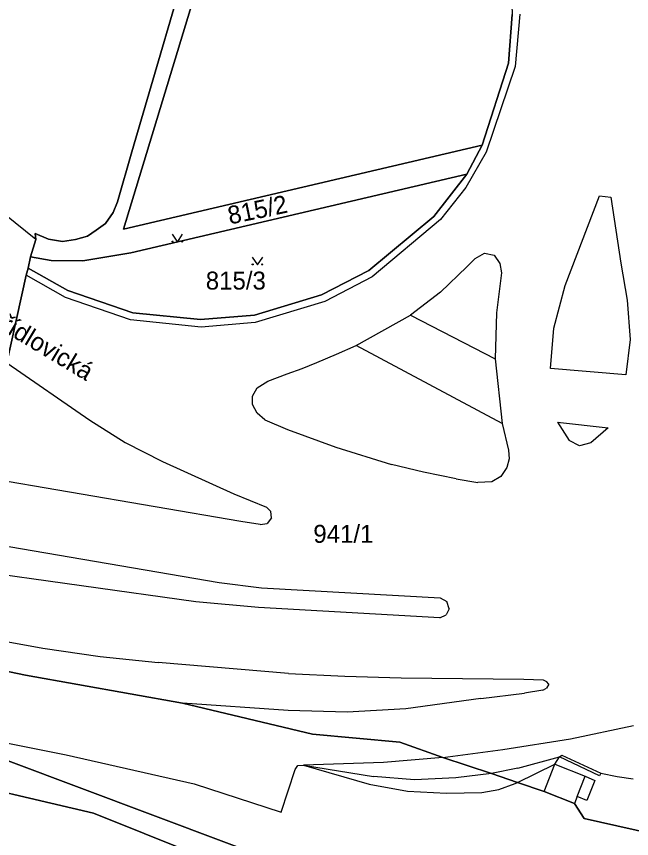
# Model space of a CAD drawing. Extents: x -598934 to -598196, y -1162208 to -1161502.
# Drawn here: x -598332.2 to -598274, y -1162056.4 to -1161978.6 of the extents above; entities that cross this region are included whole.
import ezdxf

# ---------------------------------------------------------------- set-up
doc = ezdxf.new("R2010")
doc.units = 0
for name, color, linetype in [('KN_CAR_KR', 7, 'Continuous'), ('KN_KULTURY', 7, 'Continuous'), ('KN_PARC_CIS_POM', 7, 'Continuous'), ('KN_PARC_CIS_POZ', 7, 'Continuous'), ('KN_PARC_PLOCHA', 7, 'Continuous'), ('KN_ULICE', 7, 'Continuous'), ('parcely_l', 7, 'Continuous')]:
    doc.layers.add(name, color=color, linetype=linetype)

msp = doc.modelspace()

# ---------------------------------------------------------------- linework, layer by layer
at = {"layer": 'KN_CAR_KR'}
for points in [[(-598330.34, -1161999.7), (-598362.46, -1161973.78)], [(-598284.56, -1161978.37), (-598284.98, -1161983.3)], [(-598284.98, -1161983.3), (-598287.75, -1161991.43)], [(-598287.75, -1161991.43), (-598289.66, -1161994.78)], [(-598289.66, -1161994.78), (-598292.05, -1161997.81)], [(-598280.26, -1162004.04), (-598277, -1161995.55)], [(-598277, -1161995.55), (-598275.94, -1161995.69)], [(-598275.94, -1161995.69), (-598275, -1162001.93)], [(-598292.05, -1161997.81), (-598298.51, -1162003.24)], [(-598288.78, -1162001.5), (-598287.89, -1162000.99)], [(-598287.89, -1162000.99), (-598286.98, -1162001.16)], [(-598286.98, -1162001.16), (-598286.44, -1162001.96)], [(-598289.55, -1162002.29), (-598288.78, -1162001.5)], [(-598286.44, -1162001.96), (-598286.27, -1162002.85)], [(-598275, -1162001.93), (-598274.38, -1162005.44)], [(-598289.55, -1162002.29), (-598292.05, -1162004.69)], [(-598286.27, -1162002.85), (-598286.75, -1162006.62)], [(-598327.56, -1162005.17), (-598331.27, -1162003.07)], [(-598298.51, -1162003.24), (-598303, -1162005.55)], [(-598281.32, -1162008.09), (-598280.26, -1162004.04)], [(-598321.4, -1162007.29), (-598327.56, -1162005.17)], [(-598292.05, -1162004.69), (-598294.9, -1162006.84)], [(-598303, -1162005.55), (-598309.61, -1162007.55)], [(-598274.38, -1162005.44), (-598274.12, -1162009.16)], [(-598286.75, -1162006.62), (-598286.89, -1162011)], [(-598314.7, -1162007.98), (-598321.4, -1162007.29)], [(-598309.61, -1162007.55), (-598314.7, -1162007.98)], [(-598300.04, -1162009.73), (-598294.9, -1162006.84)], [(-598294.9, -1162006.84), (-598286.89, -1162011)], [(-598281.66, -1162011.9), (-598281.32, -1162008.09)], [(-598301.9, -1162010.54), (-598300.04, -1162009.73)], [(-598286.23, -1162017.12), (-598300.04, -1162009.73)], [(-598274.12, -1162009.16), (-598274.51, -1162012.5)], [(-598303.76, -1162011.35), (-598301.9, -1162010.54)], [(-598333.11, -1162011.38), (-598325.26, -1162016.8)], [(-598305.16, -1162011.9), (-598303.76, -1162011.35)], [(-598286.89, -1162011), (-598286.23, -1162017.12)], [(-598306.57, -1162012.42), (-598305.16, -1162011.9)], [(-598274.51, -1162012.5), (-598281.66, -1162011.9)], [(-598308.39, -1162013.09), (-598306.57, -1162012.42)], [(-598309.86, -1162014.51), (-598309.42, -1162013.75)], [(-598309.42, -1162013.75), (-598308.39, -1162013.09)], [(-598309.86, -1162015.31), (-598309.86, -1162014.51)], [(-598309.42, -1162016.14), (-598309.86, -1162015.31)], [(-598308.69, -1162016.78), (-598309.42, -1162016.14)], [(-598325.26, -1162016.8), (-598321.9, -1162018.92)], [(-598308.69, -1162016.78), (-598306.54, -1162017.69)], [(-598306.54, -1162017.69), (-598301.97, -1162019.36)], [(-598286.23, -1162017.12), (-598285.62, -1162019.65)], [(-598280.97, -1162017), (-598276.2, -1162017.51)], [(-598280.97, -1162017), (-598279.88, -1162018.73)], [(-598276.2, -1162017.51), (-598277.82, -1162018.95)], [(-598321.9, -1162018.92), (-598318.37, -1162020.72)], [(-598278.91, -1162019.23), (-598279.88, -1162018.73)], [(-598277.82, -1162018.95), (-598278.91, -1162019.23)], [(-598301.97, -1162019.36), (-598296.7, -1162020.99)], [(-598285.62, -1162019.65), (-598285.56, -1162020.47)], [(-598318.37, -1162020.72), (-598311.61, -1162023.76)], [(-598285.56, -1162020.47), (-598285.79, -1162021.29)], [(-598293.65, -1162021.71), (-598296.7, -1162020.99)], [(-598285.79, -1162021.29), (-598286.36, -1162022.12)], [(-598310.94, -1162026.4), (-598335.31, -1162022.24)], [(-598290.58, -1162022.35), (-598293.65, -1162021.71)], [(-598290.58, -1162022.35), (-598288.53, -1162022.7)], [(-598286.36, -1162022.12), (-598287.19, -1162022.63)], [(-598287.19, -1162022.63), (-598288.53, -1162022.7)], [(-598311.61, -1162023.76), (-598308.51, -1162025.03)], [(-598308.51, -1162025.03), (-598308.1, -1162025.46)], [(-598308.05, -1162026.06), (-598308.1, -1162025.46)], [(-598308.05, -1162026.06), (-598308.46, -1162026.59)], [(-598309.12, -1162026.69), (-598310.94, -1162026.4)], [(-598309.12, -1162026.69), (-598308.46, -1162026.59)], [(-598336.43, -1162028.17), (-598312.99, -1162032.18)], [(-598315.2, -1162034.01), (-598336.9, -1162030.98)], [(-598312.99, -1162032.18), (-598309.01, -1162032.67)], [(-598309.01, -1162032.67), (-598292.09, -1162033.61)], [(-598309.28, -1162034.55), (-598315.2, -1162034.01)], [(-598292.09, -1162033.61), (-598291.45, -1162033.96)], [(-598291.25, -1162034.66), (-598291.45, -1162033.96)], [(-598292.11, -1162035.51), (-598309.28, -1162034.55)], [(-598291.25, -1162034.66), (-598291.53, -1162035.24)], [(-598292.11, -1162035.51), (-598291.53, -1162035.24)], [(-598338.01, -1162036.88), (-598329.7, -1162038.39)], [(-598329.7, -1162038.39), (-598324.26, -1162039.17)], [(-598324.26, -1162039.17), (-598318.79, -1162039.74)], [(-598306.43, -1162040.79), (-598318.79, -1162039.74)], [(-598306.43, -1162040.79), (-598301.11, -1162041.05)], [(-598301.11, -1162041.05), (-598295.78, -1162041.19)], [(-598295.78, -1162041.19), (-598284.17, -1162041.32)], [(-598284.17, -1162041.32), (-598282.33, -1162041.39)], [(-598282.33, -1162041.39), (-598282.01, -1162041.53)], [(-598281.79, -1162041.81), (-598282.01, -1162041.53)], [(-598281.79, -1162041.81), (-598282.01, -1162042.16)], [(-598282.38, -1162042.35), (-598284.1, -1162042.64)], [(-598282.38, -1162042.35), (-598282.01, -1162042.16)], [(-598288.24, -1162043.14), (-598295.33, -1162044.12)], [(-598288.24, -1162043.14), (-598284.1, -1162042.64)], [(-598306.47, -1162044.28), (-598316.47, -1162043.58)], [(-598295.33, -1162044.12), (-598300.9, -1162044.46)], [(-598300.9, -1162044.46), (-598306.47, -1162044.28)], [(-598279.75, -1162046.98), (-598273.78, -1162045.72)], [(-598339.66, -1162046.05), (-598327.47, -1162048.48)], [(-598286.15, -1162047.99), (-598279.75, -1162046.98)], [(-598291.83, -1162048.73), (-598286.15, -1162047.99)], [(-598327.47, -1162048.48), (-598315.37, -1162051.23)], [(-598291.83, -1162048.73), (-598297.45, -1162049.21)], [(-598284.75, -1162049.75), (-598280.79, -1162048.66)], [(-598281.23, -1162049.38), (-598280.79, -1162048.66)], [(-598280.79, -1162048.66), (-598280.56, -1162048.52)], [(-598277.01, -1162050.47), (-598280.79, -1162048.66)], [(-598280.56, -1162048.52), (-598276.87, -1162050.21)], [(-598305.8, -1162049.86), (-598305.56, -1162049.51)], [(-598305.56, -1162049.51), (-598305.01, -1162049.45)], [(-598297.45, -1162049.21), (-598305.01, -1162049.45)], [(-598305.01, -1162049.45), (-598298.39, -1162050.54)], [(-598305.01, -1162049.45), (-598298.81, -1162051.27)], [(-598284.77, -1162051.1), (-598281.23, -1162049.38)], [(-598282.25, -1162051.96), (-598281.23, -1162049.38)], [(-598281.23, -1162049.38), (-598278.37, -1162050.51)], [(-598307.13, -1162053.9), (-598305.8, -1162049.86)], [(-598287.23, -1162050.26), (-598290.62, -1162050.67)], [(-598284.75, -1162049.75), (-598287.23, -1162050.26)], [(-598276.87, -1162050.21), (-598277.01, -1162050.47)], [(-598276.87, -1162050.21), (-598275.35, -1162050.54)], [(-598294.51, -1162050.84), (-598298.39, -1162050.54)], [(-598290.62, -1162050.67), (-598294.51, -1162050.84)], [(-598284.98, -1162051.2), (-598284.77, -1162051.1)], [(-598279.13, -1162052.44), (-598278.37, -1162050.51)], [(-598278.37, -1162050.51), (-598277.45, -1162050.93)], [(-598277.45, -1162050.93), (-598278.2, -1162052.81)], [(-598275.35, -1162050.54), (-598273.83, -1162050.77)], [(-598315.37, -1162051.23), (-598307.13, -1162053.9)], [(-598298.81, -1162051.27), (-598295.17, -1162051.94)], [(-598295.17, -1162051.94), (-598291.48, -1162052.13)], [(-598288.15, -1162052.04), (-598286.52, -1162051.76)], [(-598286.52, -1162051.76), (-598284.98, -1162051.2)], [(-598291.48, -1162052.13), (-598288.15, -1162052.04)], [(-598279.13, -1162052.44), (-598279.39, -1162053.09)], [(-598278.2, -1162052.81), (-598279.13, -1162052.44)]]:
    msp.add_lwpolyline(points, dxfattribs=at)
at = {"layer": 'KN_KULTURY'}
for points in [[(-598317.462, -1161999.192), (-598316.962, -1161999.942), (-598316.462, -1161999.192)], [(-598309.882, -1162001.352), (-598309.382, -1162002.102), (-598308.882, -1162001.352)]]:
    msp.add_lwpolyline(points, dxfattribs=at)
for centre in [(-598317.412, -1161999.891), (-598316.513, -1161999.891), (-598309.832, -1162002.051), (-598308.933, -1162002.051)]:
    msp.add_circle(centre, 0.05, dxfattribs=at)
at = {"layer": 'KN_PARC_PLOCHA'}
for points in [[(-598288.1, -1161990.75), (-598322.07, -1161998.71), (-598315.42, -1161976.86), (-598294.91, -1161912.37), (-598291.89, -1161903.62), (-598286.96, -1161891.51), (-598272.85, -1161861.26), (-598271.79, -1161860.57), (-598281.27, -1161888.97), (-598286.42, -1161916.94), (-598287.31, -1161938.24), (-598286.7, -1161955.76), (-598285.36, -1161975.57), (-598285.26, -1161978.39), (-598285.61, -1161982.99)], [(-598331.09, -1162002.39), (-598330.87, -1162001.34), (-598328.9, -1162001.67), (-598325.91, -1162001.7), (-598321.37, -1162000.94), (-598289.55, -1161993.5), (-598292.68, -1161997.5), (-598298.83, -1162002.62), (-598303.32, -1162004.92), (-598309.67, -1162006.85), (-598314.76, -1162007.28), (-598321.17, -1162006.62), (-598327.33, -1162004.51)], [(-598263.99, -1162057.76), (-598220.05, -1162077.44), (-598195.56, -1162092.014), (-598195.56, -1162136.231), (-598205.15, -1162123.82), (-598216.54, -1162112.76), (-598257.11, -1162082.94), (-598279.75, -1162070.87), (-598298.86, -1162061.88), (-598339.73, -1162046.53), (-598339.66, -1162046.05), (-598338.47, -1162039.46), (-598331.32, -1162040.94), (-598316.47, -1162043.58), (-598304.18, -1162046.54), (-598295.91, -1162047.3), (-598291.83, -1162048.73), (-598287.23, -1162050.26), (-598284.77, -1162051.1), (-598282.25, -1162051.96), (-598279.39, -1162053.09), (-598278.46, -1162054.52)], [(-598195.56, -1162136.231), (-598195.56, -1162141.849), (-598210.14, -1162123.52), (-598229.5, -1162106.51), (-598258.47, -1162085.36), (-598291.34, -1162067.48), (-598324.91, -1162054), (-598340.53, -1162050.35), (-598339.73, -1162046.53), (-598298.86, -1162061.88), (-598279.75, -1162070.87), (-598257.11, -1162082.94), (-598216.54, -1162112.76), (-598205.15, -1162123.82)]]:
    msp.add_lwpolyline(points, close=True, dxfattribs=at)
for points in [[(-598294.91, -1161912.37), (-598315.42, -1161976.86), (-598322.07, -1161998.71), (-598288.1, -1161990.75), (-598289.55, -1161993.5), (-598321.37, -1162000.94), (-598325.91, -1162001.7), (-598328.9, -1162001.67), (-598330.87, -1162001.34), (-598330.34, -1161999.7), (-598330.42, -1161999.13), (-598329.17, -1161999.67), (-598327.84, -1161999.87), (-598326.6, -1161999.69), (-598325.46, -1161999.37), (-598324.63, -1161998.8), (-598323.76, -1161998.16), (-598323.03, -1161997.13), (-598322.64, -1161996.12), (-598321.28, -1161991.38), (-598308.6, -1161948.05), (-598296.97, -1161912.35)], [(-598308.6, -1161948.05), (-598321.28, -1161991.38), (-598322.64, -1161996.12), (-598323.03, -1161997.13), (-598323.76, -1161998.16), (-598324.63, -1161998.8), (-598325.46, -1161999.37), (-598326.6, -1161999.69), (-598327.84, -1161999.87), (-598329.17, -1161999.67), (-598330.42, -1161999.13), (-598330.34, -1161999.7), (-598330.87, -1162001.34), (-598331.09, -1162002.39), (-598331.27, -1162003.07), (-598333.11, -1162011.38)], [(-598333.11, -1162011.38), (-598331.27, -1162003.07), (-598331.09, -1162002.39), (-598327.33, -1162004.51), (-598321.17, -1162006.62), (-598314.76, -1162007.28), (-598309.67, -1162006.85), (-598303.32, -1162004.92), (-598298.83, -1162002.62), (-598292.68, -1161997.5), (-598289.55, -1161993.5), (-598288.1, -1161990.75), (-598285.61, -1161982.99), (-598285.26, -1161978.39)], [(-598263.99, -1162057.76), (-598278.46, -1162054.52), (-598279.39, -1162053.09), (-598282.25, -1162051.96), (-598284.77, -1162051.1), (-598287.23, -1162050.26), (-598291.83, -1162048.73), (-598295.91, -1162047.3), (-598304.18, -1162046.54), (-598316.47, -1162043.58), (-598331.32, -1162040.94), (-598338.47, -1162039.46)], [(-598342.48, -1162057.27), (-598341.1, -1162052.1), (-598340.53, -1162050.35), (-598324.91, -1162054), (-598291.34, -1162067.48)]]:
    msp.add_lwpolyline(points, dxfattribs=at)
at = {"layer": 'parcely_l'}
for points in [[(-598288.1, -1161990.75), (-598322.07, -1161998.71), (-598315.42, -1161976.86), (-598294.91, -1161912.37), (-598291.89, -1161903.62), (-598286.96, -1161891.51), (-598272.85, -1161861.26), (-598271.79, -1161860.57)], [(-598271.79, -1161860.57), (-598281.27, -1161888.97), (-598286.42, -1161916.94), (-598287.31, -1161938.24), (-598286.7, -1161955.76), (-598285.36, -1161975.57), (-598285.26, -1161978.39), (-598285.61, -1161982.99), (-598288.1, -1161990.75)], [(-598295.82, -1161909.22), (-598296.97, -1161912.35), (-598308.6, -1161948.05), (-598321.28, -1161991.38), (-598322.64, -1161996.12), (-598323.03, -1161997.13), (-598323.76, -1161998.16), (-598324.63, -1161998.8), (-598325.46, -1161999.37), (-598326.6, -1161999.69), (-598327.84, -1161999.87), (-598329.17, -1161999.67), (-598330.42, -1161999.13), (-598330.34, -1161999.7), (-598330.87, -1162001.34)], [(-598288.1, -1161990.75), (-598289.55, -1161993.5)], [(-598289.55, -1161993.5), (-598292.68, -1161997.5), (-598298.83, -1162002.62), (-598303.32, -1162004.92), (-598309.67, -1162006.85), (-598314.76, -1162007.28), (-598321.17, -1162006.62), (-598327.33, -1162004.51), (-598331.09, -1162002.39)], [(-598330.87, -1162001.34), (-598328.9, -1162001.67), (-598325.91, -1162001.7), (-598321.37, -1162000.94), (-598289.55, -1161993.5)], [(-598330.87, -1162001.34), (-598331.09, -1162002.39)], [(-598331.09, -1162002.39), (-598331.27, -1162003.07), (-598333.11, -1162011.38), (-598334.46, -1162017.5), (-598335.19, -1162021.63), (-598335.31, -1162022.24), (-598336.43, -1162028.17), (-598336.52, -1162028.66), (-598336.81, -1162030.49), (-598336.9, -1162030.98), (-598338.01, -1162036.88), (-598338.1, -1162037.34), (-598338.44, -1162039.26), (-598338.47, -1162039.46)], [(-598338.47, -1162039.46), (-598331.32, -1162040.94), (-598316.47, -1162043.58), (-598304.18, -1162046.54), (-598295.91, -1162047.3), (-598291.83, -1162048.73), (-598287.23, -1162050.26), (-598284.77, -1162051.1), (-598282.25, -1162051.96), (-598279.39, -1162053.09), (-598278.46, -1162054.52), (-598263.99, -1162057.76)], [(-598339.73, -1162046.53), (-598298.86, -1162061.88), (-598279.75, -1162070.87), (-598257.11, -1162082.94), (-598216.54, -1162112.76), (-598205.15, -1162123.82), (-598195.56, -1162136.231)], [(-598195.56, -1162141.849), (-598210.14, -1162123.52), (-598229.5, -1162106.51), (-598258.47, -1162085.36), (-598291.34, -1162067.48), (-598324.91, -1162054), (-598340.53, -1162050.35)]]:
    msp.add_lwpolyline(points, dxfattribs=at)

# ---------------------------------------------------------------- texts
at = {"layer": 'KN_PARC_CIS_POM'}
msp.add_text('941/1', height=1.7, dxfattribs=at).set_placement((-598304.092, -1162028.41))
at = {"layer": 'KN_PARC_CIS_POZ'}
msp.add_text('815/2', height=1.7, rotation=11.69938, dxfattribs=at).set_placement((-598311.993, -1161998.273))
msp.add_text('815/3', height=1.7, dxfattribs=at).set_placement((-598314.272, -1162004.43))
at = {"layer": 'KN_ULICE'}
msp.add_text('Křídlovická', height=1.7, rotation=329.04728, dxfattribs=at).set_placement((-598335.113, -1162007.396))

doc.saveas('drawing.dxf')
